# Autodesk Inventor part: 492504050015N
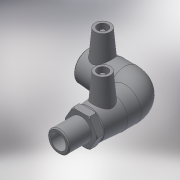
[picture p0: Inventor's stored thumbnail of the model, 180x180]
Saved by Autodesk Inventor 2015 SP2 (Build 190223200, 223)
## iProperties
Created: 2017-06
Part Number: 492504050015N
Material: Generic
Description: PLASSON 90° ELBOW MALE TRANSITION 50 x 11⁄2"
Document SubType Name: Modeling
Designer: KIM
Mass: 349.613 g
Surface Area: 758.424 cm^2
Volume: 349.613 cm^3
Density: 1 g/cm^3
Appearance: Default
Author: KIM
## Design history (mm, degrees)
derived "492504.ipt"
feature "Solid1::492504.ipt"
tag "TaggingFeature1"
body "Solid1"
other parameters: "d2" = 67, "d4" = 37, "d5" = 60.3, "d8" = 168 deg, "d10" = 19.6, "d11" = 6.53333, "d29" = 52, "d30" = 15, "d31" = 61.05, "d34" = 5 deg, "d41" = 4, "d42" = 14, "d43" = 0, "d48" = 77.5, "d50" = 42.5, "d51" = 19.6, "d52" = 49, "d54" = 90 deg, "d58" = 49, "d59" = 0, "d61" = 90 deg, "d86" = 3, "d87" = 0, "d93" = 0.1, "d94" = 15.75, "d95" = 47.803, "d96" = 33.4621, "d97" = 35, "d98" = 63, "d99" = 67, "d100" = 56.7, "d102" = 2.5, "d106" = 0, "L_" = 174, "L_1" = 49, "D_" = 35, "A_" = 52, "d_2" = 12, "L_2" = 63, "D_1" = 67, "R_" = 47.803
